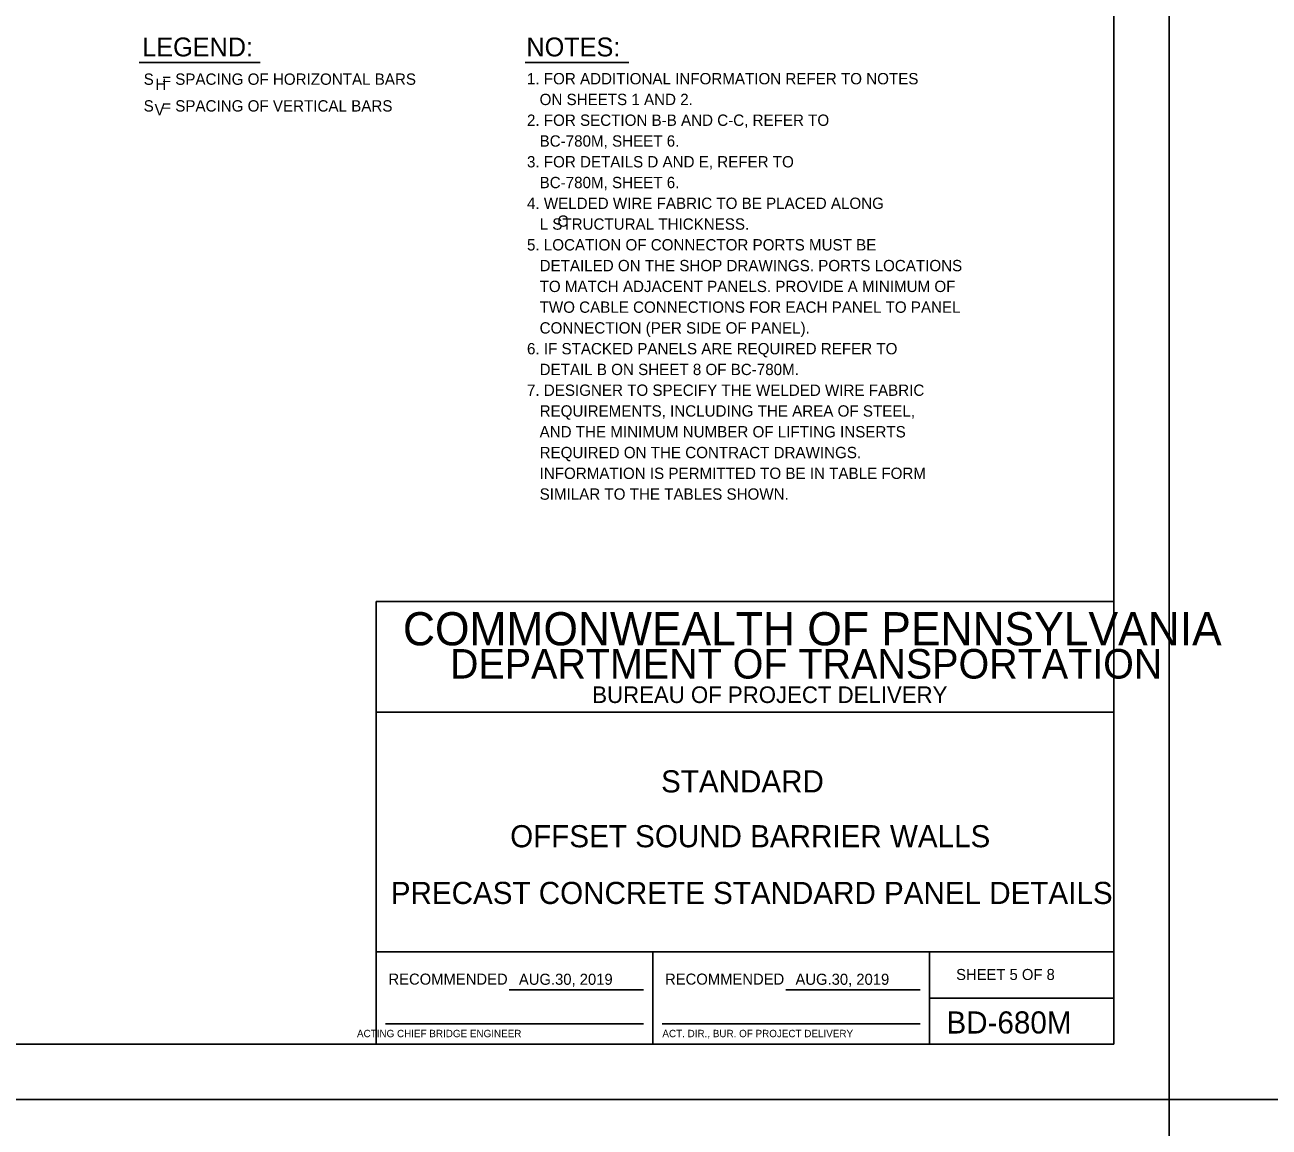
# Model space of a CAD drawing. Extents: x 3385 to 6532, y -616 to 1166.
# Drawn here: x 5133.1 to 5470.5, y -29.8 to 269.1 of the extents above; entities that cross this region are included whole.
import ezdxf

# ---------------------------------------------------------------- set-up
doc = ezdxf.new("R2010")
doc.units = 0
for name, color, linetype in [('1', 7, 'Continuous'), ('2', 7, 'Continuous'), ('PLT-BNDY', 7, 'Continuous')]:
    doc.layers.add(name, color=color, linetype=linetype)

msp = doc.modelspace()

# ---------------------------------------------------------------- linework, layer by layer
at = {"layer": '1'}
for p, q in [((5164.1, 258.89), (5196.9, 258.89)), ((5268.73, 258.89), (5296.8, 258.89)), ((5303.34, -7.31), (5303.34, 17.69)), ((5264.43, 7.41), (5300.84, 7.41)), ((5339.43, 7.41), (5375.84, 7.41)), ((5230.84, -1.81), (5300.84, -1.81)), ((5305.84, -1.81), (5375.84, -1.81))]:
    msp.add_line(p, q, dxfattribs=at)
at = {"layer": '2'}
for p, q in [((5428.34, 556.69), (5428.34, -7.31)), ((5428.34, 112.69), (5228.34, 112.69)), ((5228.34, 112.69), (5228.34, -7.31)), ((5428.34, -7.31), (5428.34, 112.69)), ((5428.34, 82.69), (5228.34, 82.69)), ((5428.34, 17.69), (5228.34, 17.69)), ((5378.34, 17.69), (5378.34, -7.31)), ((5378.34, 5.19), (5428.34, 5.19)), ((5428.34, -7.31), (4642.34, -7.31)), ((5228.34, -7.31), (5428.34, -7.31))]:
    msp.add_line(p, q, dxfattribs=at)
at = {"layer": 'PLT-BNDY'}
for points in [[(4602.34, 571.69), (5443.34, 571.69), (5443.34, -22.31), (4602.34, -22.31)], [(5443.34, 571.69), (6284.34, 571.69), (6284.34, -22.31), (5443.34, -22.31)], [(4602.34, -22.31), (5443.34, -22.31), (5443.34, -616.31), (4602.34, -616.31)], [(5443.34, -22.31), (6284.34, -22.31), (6284.34, -616.31), (5443.34, -616.31)]]:
    msp.add_lwpolyline(points, close=True, dxfattribs=at)

# ---------------------------------------------------------------- texts
at = {"layer": '1'}
for s, height, p in [('LEGEND:', 5.117, (5164.9, 260.51)), ('NOTES:', 5.117, (5269.07, 260.51)), ('S  = SPACING OF HORIZONTAL BARS', 3.072, (5165.29, 252.81)), ('H', 3.07, (5168.44, 251.43)), ('1. FOR ADDITIONAL INFORMATION REFER TO NOTES', 3.072, (5269.23, 252.94)), ('   ON SHEETS 1 AND 2.', 3.072, (5269.23, 247.31)), ('S  = SPACING OF VERTICAL BARS', 3.072, (5165.29, 245.56)), ('V', 3.07, (5168.24, 244.55)), ('2. FOR SECTION B-B AND C-C, REFER TO', 3.072, (5269.23, 241.68)), ('   BC-780M, SHEET 6.', 3.072, (5269.23, 236.04)), ('3. FOR DETAILS D AND E, REFER TO', 3.072, (5269.23, 230.41)), ('   BC-780M, SHEET 6.', 3.072, (5269.23, 224.78)), ('4. WELDED WIRE FABRIC TO BE PLACED ALONG', 3.072, (5269.23, 219.15)), ('   L STRUCTURAL THICKNESS.', 3.072, (5269.23, 213.52)), ('C', 3.07, (5277.48, 214.33)), ('5. LOCATION OF CONNECTOR PORTS MUST BE', 3.072, (5269.23, 207.89)), ('   DETAILED ON THE SHOP DRAWINGS. PORTS LOCATIONS', 3.072, (5269.23, 202.26)), ('   TO MATCH ADJACENT PANELS. PROVIDE A MINIMUM OF', 3.072, (5269.23, 196.62)), ('   TWO CABLE CONNECTIONS FOR EACH PANEL TO PANEL', 3.072, (5269.23, 190.99)), ('   CONNECTION (PER SIDE OF PANEL).', 3.072, (5269.23, 185.36)), ('6. IF STACKED PANELS ARE REQUIRED REFER TO', 3.072, (5269.23, 179.73)), ('   DETAIL B ON SHEET 8 OF BC-780M.', 3.072, (5269.23, 174.1)), ('7. DESIGNER TO SPECIFY THE WELDED WIRE FABRIC', 3.072, (5269.23, 168.47)), ('   REQUIREMENTS, INCLUDING THE AREA OF STEEL,', 3.072, (5269.23, 162.84)), ('   AND THE MINIMUM NUMBER OF LIFTING INSERTS', 3.072, (5269.23, 157.2)), ('   REQUIRED ON THE CONTRACT DRAWINGS.', 3.072, (5269.23, 151.57)), ('   INFORMATION IS PERMITTED TO BE IN TABLE FORM', 3.072, (5269.23, 145.94)), ('   SIMILAR TO THE TABLES SHOWN.', 3.072, (5269.23, 140.31)), ('STANDARD', 6, (5305.59, 60.94)), ('OFFSET SOUND BARRIER WALLS', 6.0001, (5264.67, 46.07)), ('PRECAST CONCRETE STANDARD PANEL DETAILS', 6.0001, (5232.3, 30.69)), ('RECOMMENDED', 3, (5231.67, 8.82)), ('AUG.30, 2019', 3, (5267.03, 8.78)), ('RECOMMENDED', 3, (5306.67, 8.82)), ('AUG.30, 2019', 3, (5342.03, 8.78)), ('SHEET 5 OF 8', 3, (5385.59, 10.08)), ('BD-680M', 6, (5382.97, -4.43)), ('       ACTING CHIEF BRIDGE ENGINEER', 2.0002, (5217.93, -5.43)), ('ACT. DIR., BUR. OF PROJECT DELIVERY', 2.0002, (5305.94, -5.43))]:
    msp.add_text(s, height=height, dxfattribs=at).set_placement(p)
at = {"layer": '2'}
for s, height, p in [('COMMONWEALTH OF PENNSYLVANIA', 9, (5235.59, 100.82)), ('DEPARTMENT OF TRANSPORTATION', 8.0002, (5248.34, 91.82)), ('BUREAU OF PROJECT DELIVERY', 4.5, (5286.93, 85.19))]:
    msp.add_text(s, height=height, dxfattribs=at).set_placement(p)

doc.saveas('drawing.dxf')
